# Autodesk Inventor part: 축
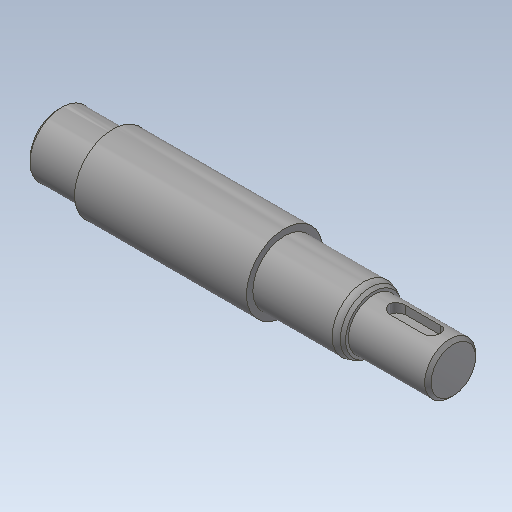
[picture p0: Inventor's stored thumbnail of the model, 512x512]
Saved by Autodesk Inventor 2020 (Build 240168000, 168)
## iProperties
Created: 2016-06
Part Number: 축
Material: 강철, 연강
Document SubType Name: Modeling
Designer: mduedu
Density: 7.86 g/cm^3
Appearance: 강철
Author: mduedu
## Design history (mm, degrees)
sketch "스케치1"
  geometry: L1 (-62, 0)-(62, 0); L2 (-62, 0)-(-62, 10); L3 (-62, 10)-(-45, 10); L4 (-45, 10)-(-45, 12); L5 (-45, 12)-(9, 12); L6 (9, 12)-(9, 10); L7 (9, 10)-(37, 10); L8 (37, 10)-(37, 8); L9 (37, 8)-(62, 8); L10 (62, 8)-(62, 0); 2 further points
  constraints: 20 end point, 5 parallel, 2 perpendicular, 1 coincident, 1 collinear, 1 horizontal, 1 midpoint, 1 vertical
  dimensions: "d0" = 124 distance of L1.start L1.end; "d2" = 16 diameter of L9 L1; "d3" = 20 diameter of L7 L1; "d4" = 24 diameter of L5 L1; "d5" = 20 diameter of L3 L1; "d6" = 17 distance of L2.end L3.end; "d7" = 25 distance of L8.end L9.end; "d8" = 53 distance from line of L5.end L10
revolve "회전1" sketch "스케치1" stored, may be unused: angle "d9" = 90 deg
chamfer "모따기1" distance "d10" = 2; stored, may be unused: second distance "d11" = 2, angle "d12" = 30 deg
fillet "모깎기1" dims "d13" = 4
node "작업 평면1"
sketch "스케치2"
  geometry: L1 (-5, 2.5)-(6, 2.5); L2 (6, -2.5)-(-5, -2.5); L3 (-5, 0)-(6, 0); L4 (-12.5, 8.845)-(-12.5, -8.845) reference; A1 r 2.5 centre (-5, 0) between (-5, 2.5) and (-5, -2.5); A2 r 2.5 centre (6, 0) between (6, -2.5) and (6, 2.5); 1 further point
  constraints: 6 end point, 4 point on circle, 3 tangent, 2 centre point, 2 parallel, 1 horizontal, 1 horizontal alignment
  dimensions: "d14" = 5 distance edge to line of A1 L4; "d15" = 5 distance between parallel lines of L2 L1; "d16" = 16 dimension on A2 A1
extrude "돌출1" cut sketch "스케치2" distance "d17" = 3; taper "d18" = 0 deg
chamfer "모따기2" distance "d19" = 1; stored, may be unused: second distance "d20" = 2, angle "d21" = 30 deg
sketch "스케치3"
  geometry: L1 (-37, -8)-(-61, -8) reference; L2 (-62, -7)-(-62, 7) reference; L3 (-38.5, -8)-(-40, -6.5); L4 (-40, -6.5)-(-40, -8); L5 (-38.5, -8)-(-40, -8); 1 further point
  constraints: 6 end point, 2 point on line, 1 collinear, 1 vertical
  dimensions: "d22" = 45 deg angle of L4 L3; "d23" = 22 distance between parallel lines of L2 L4; "d24" = 3 diameter of L3.start L4
revolve "회전2" stored, may be unused: angle "d25" = 90 deg
node "작업점1"
sketch "스케치4"
  geometry: 1 further point
hole "구멍1" sketch "스케치4" at (0, 0) diameter "d26" = 3.242; stored, may be unused: countersink angle "d30" = 90 deg, drill point angle "d32" = 120 deg; dims "d27" = 8, "d28" = 4, "d29" = 2, "d31" = 11
chamfer "모따기3" distance "d33" = 2; stored, may be unused: second distance "d34" = 2, angle "d35" = 30 deg
node "솔리드1"
pattern_circular "원형 패턴1" dims angle "d37" = 90 deg
node "작업점2"
